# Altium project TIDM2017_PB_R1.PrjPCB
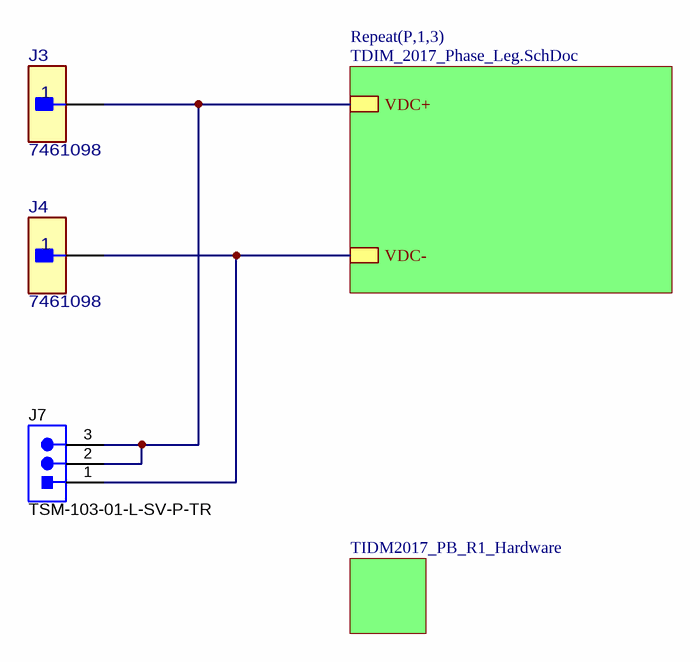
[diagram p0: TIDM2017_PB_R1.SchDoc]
CopyrightYear: 2023; PCB_Layout: Bhanu V; PCB_Rev: R1; PRJ_Customer: Public Release; PRJ_Engineer: Bhanu V; PRJ_Number: TIDM-2017_PB; PRJ_Title: 2W_Traction_Reference_Design; SCH_Rev: R1; TechSupport: http://www.ti.com/support; TID: 2017
3 sheets, 118 parts. Net scope: hierarchical (ports join the sheet entries above them; power ports are global).
Board file: TIDM2017_PB_R1.PcbDoc
Sheets:
  TIDM2017_PB_R1.SchDoc
    P1 = TDIM_2017_Phase_Leg.SchDoc
    P2 = TDIM_2017_Phase_Leg.SchDoc
    P3 = TDIM_2017_Phase_Leg.SchDoc
    Designator = TIDM2017_PB_R1_Hardware.SchDoc

## Sheet TIDM2017_PB_R1.SchDoc
size 431 x 279 mm; Date: Not shown in title block; ApprovedBy: Not shown in title block; CheckedBy: Not shown in title block; Author: Not shown in title block; CompanyName: Not shown in title block; DrawnBy: Bhanu V; Engineer: Not shown in title block; Organization: Not shown in title block; Address1: Not shown in title block; Address2: Not shown in title block; Address3: Not shown in title block; Address4: Not shown in title block; DocumentNumber: 2; Revision: Use project parameter SCH_Rev; SheetNumber: 1; SheetTotal: 2; PageSetup: Record=PageOptions¦CenterHorizontal=True¦CenterVertical=True¦PrintScale=1.00¦XCorrection=1.00¦YCorrection=1.00¦PrintKind=0¦BorderSize=5000000¦LeftOffset=0¦BottomOffset=0¦Orientation=2¦PaperLength=1000¦PaperWidth=1000¦Scale=100¦PaperSource=15¦PrintQuality=600¦MediaType=1¦DitherType=10¦PaperKind=Letter¦PrintScaleMode=1

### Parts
J3  7461098  [FP-7461098_TERM_REDCUBE_M6-MFG]
J4  7461098  [FP-7461098_TERM_REDCUBE_M6-MFG]
J7  TSM-103-01-L-SV-P-TR  [Samtec_TSM-103-01-x-SV-P]

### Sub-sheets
Designator = TIDM2017_PB_R1_Hardware: no entries
Repeat(P,1,3) = TDIM_2017_Phase_Leg.SchDoc: VDC+, VDC-

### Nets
D_HS: J3.1 J7.2 J7.3 ; sheet Repeat(P,1,3)/VDC+
S_LS: J4.1 J7.1 ; sheet Repeat(P,1,3)/VDC-

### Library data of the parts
J3 J4 = CMP-0093152-1: Conn Terminal M 1 POS Press Fit ST 25 Terminal 1 Port; Manufacturer: Wurth Electronics; SizeZ_mm: 15.7mm; Conn Gender: Male; AEC Qualified: No; Current_A: 250A; Conn Orientation: Straight; ContactFinish: Tin
J7 = CMP-0055592-1: Header, 2.54mm, 3x1, Gold, SMT; Manufacturer: Samtec; CNHeader: TRUE; Current_A: 5.4A; Shrouded: N; Gender: Male; Cert_CSA: Y; Voltage_V: 475V; Row_Count: 1; Pitch_mm: 2.54; CT: FALSE; System: Connector

## Sheet TDIM_2017_Phase_Leg.SchDoc
size 431 x 279 mm; Date: Not shown in title block; ApprovedBy: Not shown in title block; CheckedBy: Not shown in title block; Author: Not shown in title block; CompanyName: Not shown in title block; Engineer: Not shown in title block; Organization: Not shown in title block; Address1: Not shown in title block; Address2: Not shown in title block; Address3: Not shown in title block; Address4: Not shown in title block; DocumentNumber: 2; Revision: Use project parameter SCH_Rev; SheetNumber: 2; SheetTotal: 3; PageSetup: Record=PageOptions¦CenterHorizontal=True¦CenterVertical=True¦PrintScale=1.00¦XCorrection=1.00¦YCorrection=1.00¦PrintKind=0¦BorderSize=5000000¦LeftOffset=0¦BottomOffset=0¦Orientation=2¦PaperLength=1000¦PaperWidth=1000¦Scale=100¦PaperSource=15¦PrintQuality=600¦MediaType=1¦DitherType=10¦PaperKind=Letter¦PrintScaleMode=1
Used 3 times, as channels P1, P2, P3. Parts and nets are listed once, with the designators drawn on the sheet.
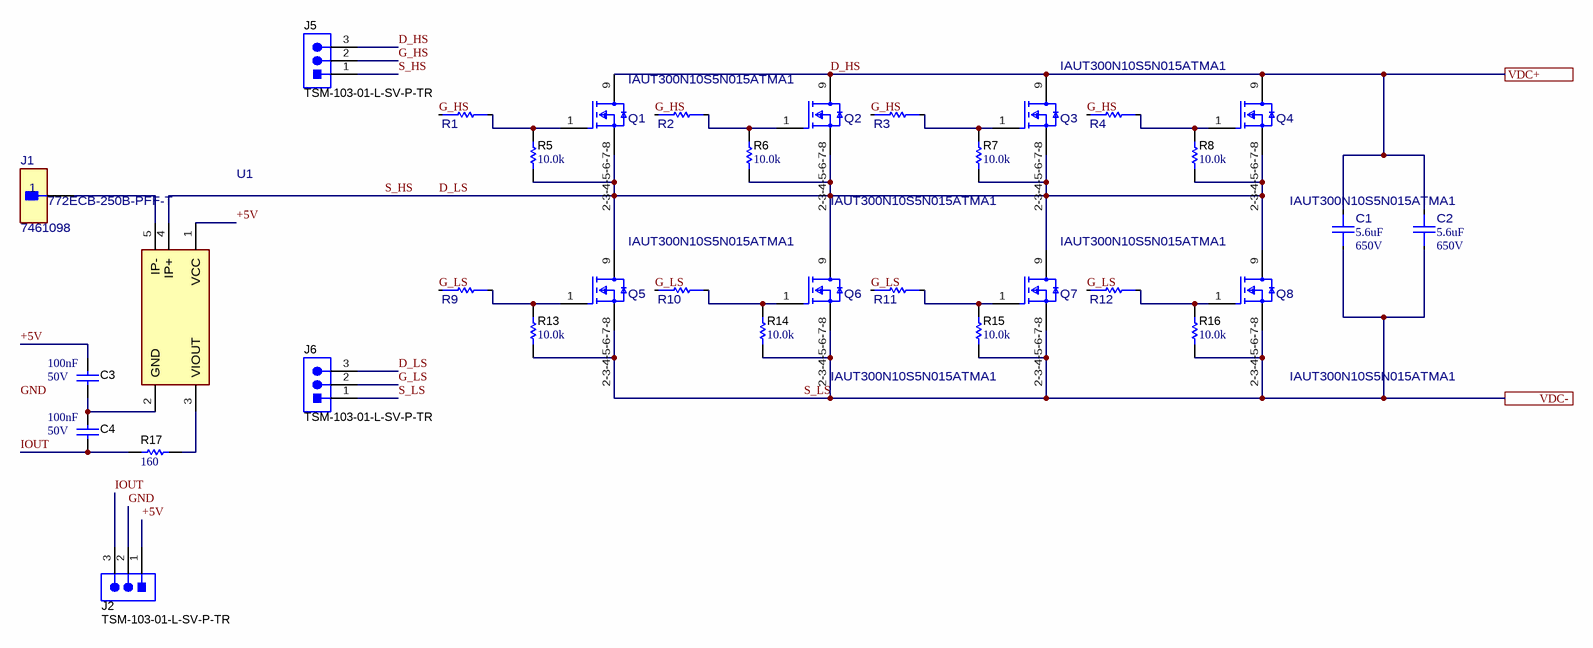
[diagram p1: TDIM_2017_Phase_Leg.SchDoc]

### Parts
C1  ValueDisplayed: 5.6uF  VDC_V: 650V  [FP-C4AQCBU4560A1XJ_RADIAL-MFG]  (hidden comment: C4AQCBU4560A1XJ)
C2  ValueDisplayed: 5.6uF  VDC_V: 650V  [FP-C4AQCBU4560A1XJ_RADIAL-MFG]  (hidden comment: C4AQCBU4560A1XJ)
C3  Cap_F: 100nF  VDC_V: 50V  [0603]  (hidden comment: 06035C104KAT2A)
C4  Cap_F: 100nF  VDC_V: 50V  [0603]  (hidden comment: 06035C104KAT2A)
J1  7461098  [FP-7461098_TERM_REDCUBE_M6-MFG]
J2  TSM-103-01-L-SV-P-TR  [Samtec_TSM-103-01-x-SV-P]
J5  TSM-103-01-L-SV-P-TR  [Samtec_TSM-103-01-x-SV-P]
J6  TSM-103-01-L-SV-P-TR  [Samtec_TSM-103-01-x-SV-P]
Q1  IAUT300N10S5N015ATMA1  [FP-IAUT300N10S5N015ATMA1_HSOF-8-MFG]
Q2  IAUT300N10S5N015ATMA1  [FP-IAUT300N10S5N015ATMA1_HSOF-8-MFG]
Q3  IAUT300N10S5N015ATMA1  [FP-IAUT300N10S5N015ATMA1_HSOF-8-MFG]
Q4  IAUT300N10S5N015ATMA1  [FP-IAUT300N10S5N015ATMA1_HSOF-8-MFG]
Q5  IAUT300N10S5N015ATMA1  [FP-IAUT300N10S5N015ATMA1_HSOF-8-MFG]
Q6  IAUT300N10S5N015ATMA1  [FP-IAUT300N10S5N015ATMA1_HSOF-8-MFG]
Q7  IAUT300N10S5N015ATMA1  [FP-IAUT300N10S5N015ATMA1_HSOF-8-MFG]
Q8  IAUT300N10S5N015ATMA1  [FP-IAUT300N10S5N015ATMA1_HSOF-8-MFG]
R1  RCS060310R0FKEA  [FP-RCS060310R0FKEA_0603-MFG]  (value not drawn)
R2  RCS060310R0FKEA  [FP-RCS060310R0FKEA_0603-MFG]  (value not drawn)
R3  RCS060310R0FKEA  [FP-RCS060310R0FKEA_0603-MFG]  (value not drawn)
R4  RCS060310R0FKEA  [FP-RCS060310R0FKEA_0603-MFG]  (value not drawn)
R5  ValueDisplayed: 10.0k  [TNPW0603]  (hidden comment: TNPW060310K0BEEA)
R6  ValueDisplayed: 10.0k  [TNPW0603]  (hidden comment: TNPW060310K0BEEA)
R7  ValueDisplayed: 10.0k  [TNPW0603]  (hidden comment: TNPW060310K0BEEA)
R8  ValueDisplayed: 10.0k  [TNPW0603]  (hidden comment: TNPW060310K0BEEA)
R9  RCS060310R0FKEA  [FP-RCS060310R0FKEA_0603-MFG]  (value not drawn)
R10  RCS060310R0FKEA  [FP-RCS060310R0FKEA_0603-MFG]  (value not drawn)
R11  RCS060310R0FKEA  [FP-RCS060310R0FKEA_0603-MFG]  (value not drawn)
R12  RCS060310R0FKEA  [FP-RCS060310R0FKEA_0603-MFG]  (value not drawn)
R13  ValueDisplayed: 10.0k  [TNPW0603]  (hidden comment: TNPW060310K0BEEA)
R14  ValueDisplayed: 10.0k  [TNPW0603]  (hidden comment: TNPW060310K0BEEA)
R15  ValueDisplayed: 10.0k  [TNPW0603]  (hidden comment: TNPW060310K0BEEA)
R16  ValueDisplayed: 10.0k  [TNPW0603]  (hidden comment: TNPW060310K0BEEA)
R17  ValueDisplayed: 160  [0603]  (hidden comment: RT0603DRE07160RL)
U1  ACS772ECB-250B-PFF-T  [FP-ACS772ECB-250B-PFF-T_PTH_10MM0_13MM0-MFG]

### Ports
VDC+, VDC-

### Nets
+5V: C3.1 J2.1 U1.1(VCC)
D_HS: C1.2 C2.2 J5.3 Q1.9(DRAIN) Q2.9(DRAIN) Q3.9(DRAIN) Q4.9(DRAIN) ; port VDC+
D_LS: J5.1 J6.3 Q1.2-3-4-5-6-7-8(SOURCE) Q2.2-3-4-5-6-7-8(SOURCE) Q3.2-3-4-5-6-7-8(SOURCE) Q4.2-3-4-5-6-7-8(SOURCE) Q5.9(DRAIN) Q6.9(DRAIN) Q7.9(DRAIN) Q8.9(DRAIN) R5.1 R6.1 R7.1 R8.1 U1.4(IP+)  [also labelled S_HS]
G_HS: J5.2 R1.1 R2.1 R3.1 R4.1
G_LS: J6.2 R9.1 R10.1 R11.1 R12.1
GND: J2.2
IOUT: C4.2 J2.3 R17.1
S_LS: C1.1 C2.1 J6.1 Q5.2-3-4-5-6-7-8(SOURCE) Q6.2-3-4-5-6-7-8(SOURCE) Q7.2-3-4-5-6-7-8(SOURCE) Q8.2-3-4-5-6-7-8(SOURCE) R13.1 R14.1 R15.1 R16.1 ; port VDC-
NetC3_2: C3.2 C4.1 U1.2(GND)
NetJ1_1: J1.1 U1.5(IP-)
NetQ1_1: Q1.1(GATE) R1.2 R5.2
NetQ2_1: Q2.1(GATE) R2.2 R6.2
NetQ3_1: Q3.1(GATE) R3.2 R7.2
NetQ4_1: Q4.1(GATE) R4.2 R8.2
NetQ5_1: Q5.1(GATE) R9.2 R13.2
NetQ6_1: Q6.1(GATE) R10.2 R14.2
NetQ7_1: Q7.1(GATE) R11.2 R15.2
NetQ8_1: Q8.1(GATE) R12.2 R16.2
NetR17_2: R17.2 U1.3(VIOUT)

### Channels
P1: designators end in _P1; ports VDC+=D_HS VDC-=S_LS
P2: designators end in _P2; ports VDC+=D_HS VDC-=S_LS
P3: designators end in _P3; ports VDC+=D_HS VDC-=S_LS

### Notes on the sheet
- Labels drawn without touching a wire or pin: GND

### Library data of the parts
C1 C2 = CMP-0094169-1: 5.6 µF Film Capacitor - 650V Polypropylene (PP), Metallized Radial; Manufacturer: KEMET; Value: 5.6µF; AEC Qualified: Yes; SizeZ_mm: 25.2mm; AEC Grade: Grade 2; Tolerance_%: 5%
C3 C4 = CMP-0006802-4: CAP, CERM, 0.1 uF, 50 V, +/- 10%, X7R, 0603; Manufacturer: AVX; TaMin_C: -55°C; Polarized: N; SizeAreaWB_mm2: 4.68; Value1: Unknown; U/M: EA; Value: 0.1uF; TaMax_C: 125°C; SizeZ_mm: 1; SizeX_mm: 1.6; SizeY_mm: 0.8; SizeArea_mm2: 1.28; AEC Category: Q200
J1 = CMP-0093152-1: as J3 on sheet TIDM2017_PB_R1
J2 J5 J6 = CMP-0055592-1: as J7 on sheet TIDM2017_PB_R1
Q1-Q8 = CMP-0120643-1: 100V 300A 1.5MOHM TOLL; Manufacturer: Infineon; Threshold Vgs Max: 3.8V; Reverse Recovery Charge: 220nC; Number Of N Channels: 1; Vgs_V: 20V; TJmax_C: +175°C; VdsMax_V: 1.3V; Pulse Drain Current: 1200A; AEC Qualified: Yes; Turn On Delay Time: 29ns; Turn Off Delay Time: 70ns; QgTyp_nC: 166nC @ 10V; Power_W: 375W; Threshold Vgs Min: 2.2V; Input Capacitace At Vds: 12316pF @ 50V; ChMode: False; Rdson45_ohm: 1.3m; SizeZ_mm: 2.4mm; Typ Forward Diode Voltage: 0.9V; AEC Grade: Grade 0; Reverse Recovery Time: 90ns
R1-R4 R9-R12 = CMP-0094869-1: 10 Ohms ±1% 0.25W, 1/4W Chip Resistor 0603 (1608 Metric) Automotive AEC-Q200, Pulse Withstanding Thick Film; Manufacturer: Vishay; Value: 10; AEC Qualified: Yes; TempCo: 100ppm/°C; Power_W: 250mW; SizeZ_mm: 0.5mm; VDC_V: 75V; AEC Grade: Grade 0
R5-R8 R13-R16 = CMP-0025686-1: RES, 10.0 k, 0.1%, 0.1 W, AEC-Q200 Grade 1, 0603; Manufacturer: Vishay-Dale; Power_W: 100mW; TempCo: 25 ppm/C; Value_Code: 10k0; U/M: EA; Value: 10.0k; EIA_Code: E192; Res_ohm: 10k; SizeX_mm: 1.6; SizeY_mm: 0.85; SizeZ_mm: 0.55; Value2: 0.1W; SizeArea_mm2: 1.36; AEC Qualified: Y; VDC_V: 75V; AEC Grade: 1; AEC Category: Q200
R17 = CMP-0024720-2: RES, 160, 0.5%, 0.1 W, 0603; Manufacturer: Yageo America; Power_W: 100mW; TempCo: 50 ppm/C; Value_Code: 160R; U/M: EA; Value: 160; EIA_Code: E192; SizeX_mm: 1.6; SizeY_mm: 0.8; SizeZ_mm: 1; Value2: 0.1W; SizeArea_mm2: 1.28; VDC_V: 75V; AEC Category: Q200
U1 = CMP-0120638-1: Galvanically Isolated Current Sensor IC with 100 µΩ Current Conductor, Sensing Current 250A, Sensor Sensitivity 8mV/A; Manufacturer: Allegro MicroSystems LLC; SizeZ_mm: 7.1mm; Accuracy: 0.9%; AEC Grade: Grade 3; AEC Qualified: Yes; Max Supply Voltage: 5.5V; Min Supply Voltage: 4.5V; Operating Supply Current: 10mA; Sensing Method: Hall Effect; Sensor Output: Analog Voltage; TaMax_C: +85°C; TaMin_C: -40°C; TJmax_C: +165°C

## Sheet TIDM2017_PB_R1_Hardware.SchDoc
size 431 x 279 mm; Date: Not shown in title block; ApprovedBy: Not shown in title block; CheckedBy: Not shown in title block; Author: Not shown in title block; CompanyName: Not shown in title block; DrawnBy: Bhanu V; Engineer: Not shown in title block; Organization: Not shown in title block; Address1: Not shown in title block; Address2: Not shown in title block; Address3: Not shown in title block; Address4: Not shown in title block; DocumentNumber: 3; Revision: Use project parameter SCH_Rev; SheetNumber: 2; SheetTotal: 2; PageSetup: Record=PageOptions¦CenterHorizontal=True¦CenterVertical=True¦PrintScale=1.00¦XCorrection=1.00¦YCorrection=1.00¦PrintKind=0¦BorderSize=5000000¦LeftOffset=0¦BottomOffset=0¦Orientation=2¦PaperLength=1000¦PaperWidth=1000¦Scale=100¦PaperSource=15¦PrintQuality=600¦MediaType=1¦DitherType=10¦PaperKind=Letter¦PrintScaleMode=1
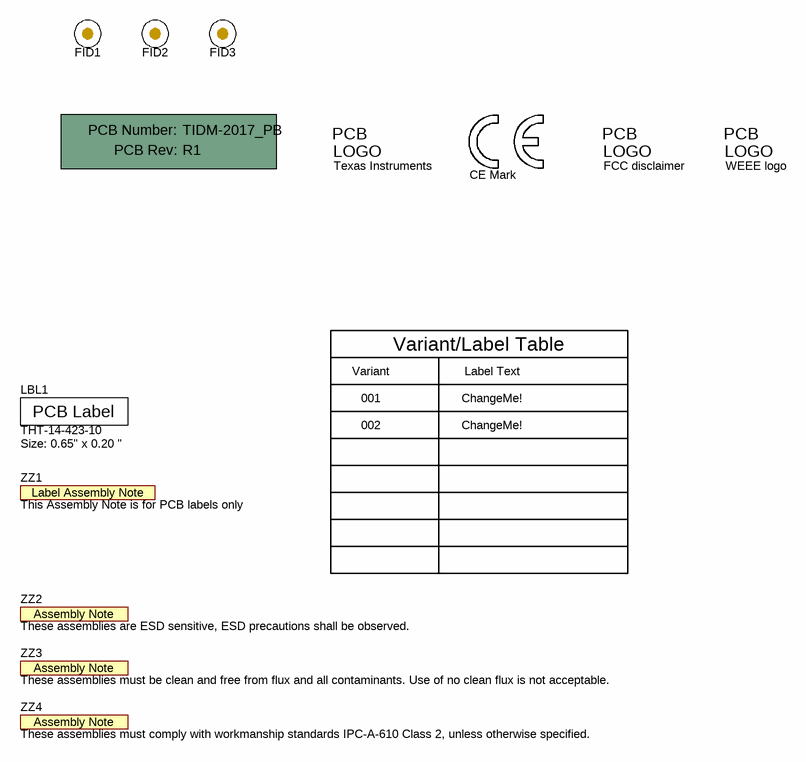
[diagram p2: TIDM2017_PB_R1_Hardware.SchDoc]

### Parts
!PCB1  Printed Circuit Board  (value not drawn)  (mechanical)
FID1  Fiducial  [Fiducial10-20]  (value not drawn)
FID2  Fiducial  [Fiducial10-20]  (value not drawn)
FID3  Fiducial  [Fiducial10-20]  (value not drawn)
LBL1  THT-14-423-10  Note: Size: 0.65" x 0.20 "  [Label_650x200]
Logo1  CE Mark  [CE_Mark_5mm]  (no BOM)
Logo2  Texas Instruments  [TI_Stacked_Overlay_Small]  (no BOM)
Logo3  FCC disclaimer  [FCC_disclaimer]  (no BOM)
Logo4  WEEE logo  [WEEE_Minimum]  (no BOM)
ZZ1  This Assembly Note is for PCB labels only  [AssemblyNoteLabel]  (no BOM)
ZZ2  These assemblies are ESD sensitive, ESD precautions shall be observed.  [AssemblyNote]  (no BOM)
ZZ3  These assemblies must be clean and free from flux and all contaminants. Use of no clean flux is not acceptable.  [AssemblyNote]  (no BOM)
ZZ4  These assemblies must comply with workmanship standards IPC-A-610 Class 2, unless otherwise specified.  [AssemblyNote]  (no BOM)

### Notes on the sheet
- Variant
- Variant/Label Table
- Label Text
- 001
- 002
- ChangeMe!

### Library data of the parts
!PCB1 = CMP-0003618-2: Manufacturer: Any; PartNumber: TIDM-2017_PB
FID1-FID3 = CMP-0077181-1: Fiducial mark.  There is nothing to buy or mount.
LBL1 = CMP-0003625-1: Thermal Transfer Printable Labels, 0.650" W x 0.200" H - 10,000 per roll; Manufacturer: Brady; CompType: Label
Logo1 = CMP-0074844-1: SymbolCreator: a0412235
Logo2 = CMP-0074838-1: Texas Instrument Corporate Signature; SymbolCreator: a0412235; Lib Reference: TI_Logo; Library Reference: Logo
Logo3 = CMP-0074847-1: FCC_disclaimer; Library Reference: Logo
Logo4 = CMP-0074769-1
ZZ1 = CMP-0003616-3
ZZ2 = CMP-0077236-1
ZZ3 = CMP-0077237-1
ZZ4 = CMP-0077238-1

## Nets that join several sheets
D_HS: TIDM2017_PB_R1 (J3.1 J7.2 J7.3), P1 (7 pins), P2 (7 pins), P3 (7 pins)
S_LS: TIDM2017_PB_R1 (J4.1 J7.1), P1 (11 pins), P2 (11 pins), P3 (11 pins)

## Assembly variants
001: not fitted FID1 FID2 FID3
